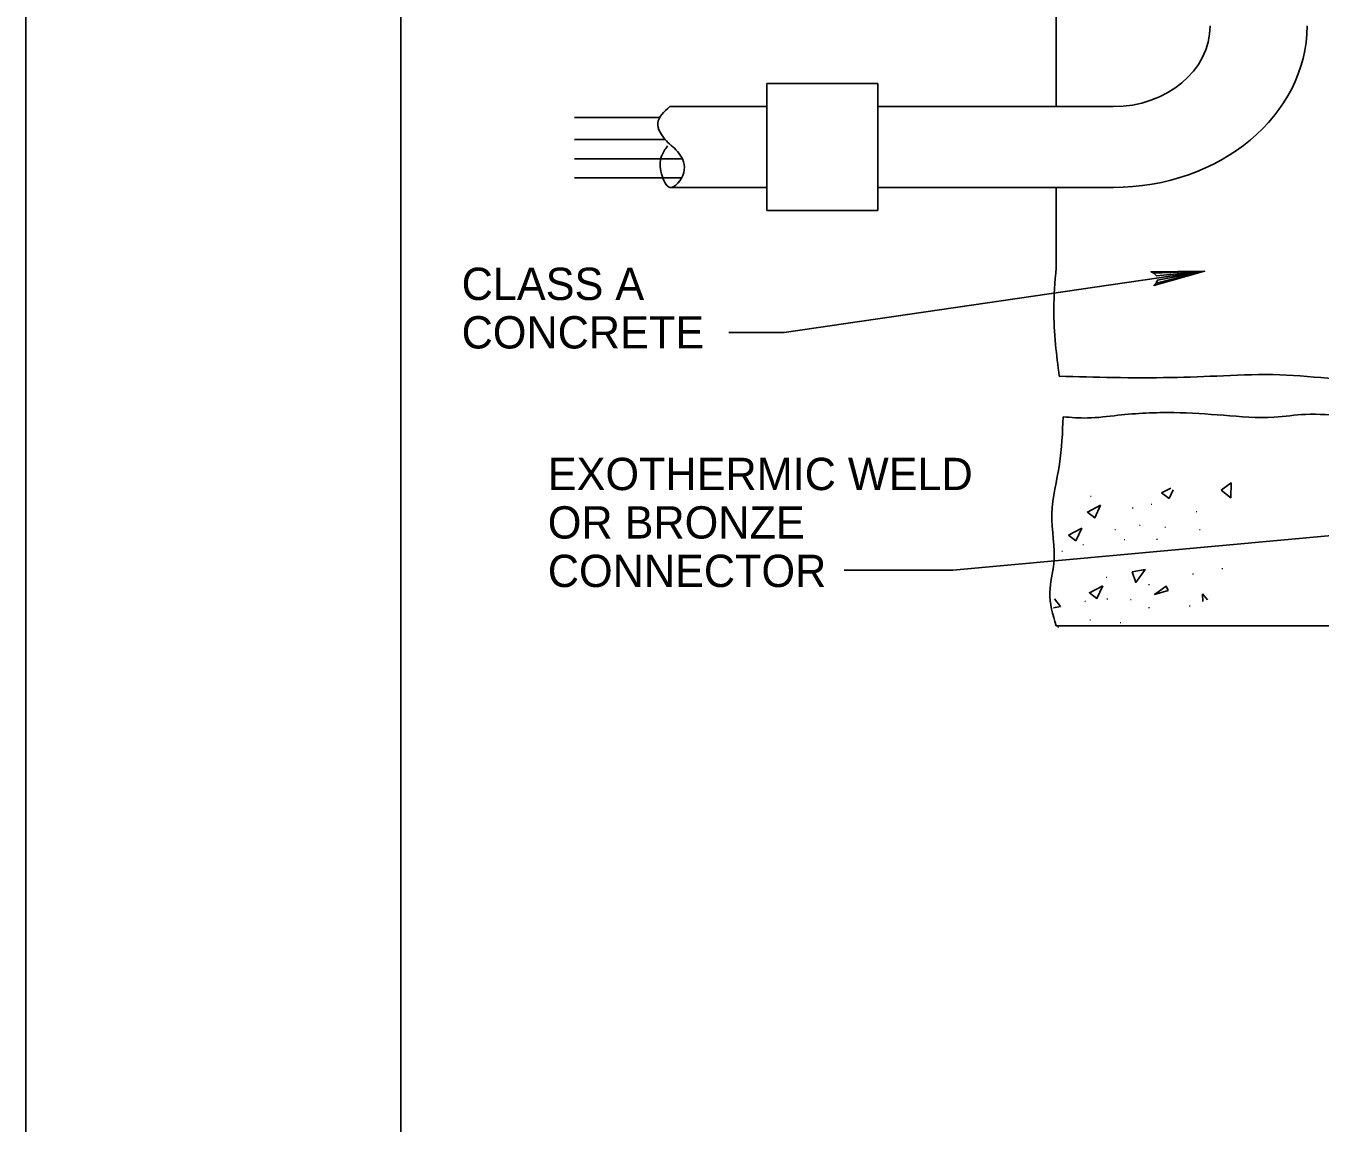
# Model space of a CAD drawing. Extents: x 638448 to 639352, y 297825 to 299013.
# Drawn here: x 638447.7 to 638582.2, y 298115.9 to 298230 of the extents above; entities that cross this region are included whole.
import ezdxf

# ---------------------------------------------------------------- set-up
doc = ezdxf.new("R2010")
doc.units = 0
for name, color, linetype in [('1', 7, 'Continuous'), ('2', 7, 'Continuous'), ('3', 7, 'Continuous'), ('PLT-BNDY', 7, 'Continuous')]:
    doc.layers.add(name, color=color, linetype=linetype)

msp = doc.modelspace()

# ---------------------------------------------------------------- linework, layer by layer
at = {"layer": '1'}
msp.add_lwpolyline([(639272.65, 297840.29), (639272.65, 298404.29), (638486.65, 298404.29), (638486.65, 297840.29), (639272.65, 297840.29), (639272.65, 297866.65), (639072.65, 297866.65), (639072.65, 297931.33), (639272.65, 297931.33), (639272.65, 297960.29), (639072.65, 297960.29), (639072.65, 297840.29), (639151.45, 297840.29), (639151.45, 297866.65), (639151.45, 297840.29), (639228.45, 297840.29), (639228.45, 297866.65), (639228.45, 297854.33), (639272.65, 297854.33)], dxfattribs=at)
at = {"layer": '2'}
for p, q in [((638554.77, 298256.25), (638554.77, 298221.59)), ((638513.54, 298220.45), (638504.71, 298220.45)), ((638524.7, 298221.59), (638514.62, 298221.59)), ((638560.7, 298221.59), (638536.22, 298221.59)), ((638514.16, 298218.17), (638504.71, 298218.17)), ((638515.9, 298216.18), (638504.71, 298216.18)), ((638515.75, 298214.18), (638504.71, 298214.18)), ((638524.7, 298213.19), (638514.62, 298213.19)), ((638560.7, 298213.19), (638536.22, 298213.19)), ((638554.77, 298213.19), (638554.77, 298204.79)), ((638554.77, 298167.59), (638589.14, 298167.59))]:
    msp.add_line(p, q, dxfattribs=at)
for points in [[(638536.22, 298210.79), (638536.22, 298223.99), (638524.7, 298223.99), (638524.7, 298210.79)], [(638571.94, 298181.71), (638572.97, 298182.46), (638572.93, 298180.91)], [(638559.4, 298180.15), (638558.02, 298179.43), (638558.8, 298178.84)], [(638562.67, 298173.22), (638564.02, 298173.45), (638563.05, 298172.11)], [(638559.62, 298171.76), (638558.24, 298171.04), (638559.02, 298170.45)], [(638566.44, 298171.27), (638566.2, 298171.73), (638565.01, 298170.87)]]:
    msp.add_lwpolyline(points, close=True, dxfattribs=at)
for points in [[(638520.74, 298198.11), (638526.5, 298198.11), (638570.21, 298204.48)], [(638564.95, 298204.27), (638565.2, 298203.99), (638570.21, 298204.48), (638564.95, 298204.27), (638564.64, 298204.42), (638570.21, 298204.48), (638565.3, 298203.56), (638565.18, 298203.22), (638570.21, 298204.48), (638564.94, 298202.98), (638565.18, 298203.22)], [(638566.7, 298181.91), (638565.74, 298181.41)], [(638565.74, 298181.41), (638566.52, 298180.83)], [(638566.52, 298180.83), (638566.94, 298181.74)], [(638532.72, 298173.38), (638544.04, 298173.38), (638589.14, 298177.5)], [(638557.43, 298177.74), (638556.05, 298177.02)], [(638556.83, 298176.43), (638557.43, 298177.74)], [(638556.05, 298177.02), (638556.83, 298176.43)], [(638570.03, 298170.12), (638570.01, 298170.93)], [(638570.01, 298170.93), (638570.51, 298170.29)], [(638555.24, 298169.6), (638554.51, 298169.46)], [(638554.62, 298170.4), (638555.24, 298169.6)]]:
    msp.add_lwpolyline(points, dxfattribs=at)
for major_axis in [(10.08, 0), (20.16, 0)]:
    msp.add_ellipse((638560.7, 298229.99), major_axis=major_axis, ratio=0.833333, start_param=4.712389, end_param=6.283185, dxfattribs=at)
for points in [[(638514.62, 298221.59), (638513.35, 298219.88), (638514.25, 298218.05), (638515.54, 298216.77), (638516.05, 298214.73), (638514.62, 298213.19), (638513.74, 298214.62), (638513.74, 298216.44), (638514.38, 298217.52)], [(638554.77, 298204.79), (638554.53, 298200.52), (638554.72, 298196.86), (638555.09, 298193.56)], [(638555.09, 298193.56), (638560.74, 298193.42), (638566.69, 298193.42), (638572.18, 298193.6), (638578.02, 298193.7), (638583.74, 298193.32), (638590.58, 298193.51), (638595.07, 298193.89), (638601.8, 298193.04), (638604.83, 298193.79), (638611.79, 298193.32), (638615.94, 298193.7), (638620.43, 298193.42), (638624.24, 298193.89), (638628.68, 298193.56)], [(638628.84, 298189.38), (638625.25, 298189.21), (638616.61, 298189.77), (638607.19, 298189.58), (638596.19, 298189.86), (638588.9, 298189.12), (638580.71, 298189.58), (638577.46, 298189.3), (638572.18, 298189.49), (638567.02, 298189.77), (638561.19, 298189.49), (638558.05, 298189.21), (638555.5, 298189.34)], [(638555.5, 298189.34), (638555.12, 298184.4), (638554.33, 298179.24), (638554.53, 298174.09), (638554.12, 298171.1), (638554.77, 298167.59)]]:
    msp.add_spline(points, degree=3, dxfattribs=at)
at = {"layer": 'PLT-BNDY'}
msp.add_lwpolyline([(638447.65, 298419.29), (639288.65, 298419.29), (639288.65, 297825.29), (638447.65, 297825.29)], close=True, dxfattribs=at)

# ---------------------------------------------------------------- texts
at = {"layer": '2'}
for p in [(638558.22, 298180.98), (638564.52, 298180.16), (638562.57, 298179.77), (638569.21, 298179.4), (638560.75, 298177.53), (638563.32, 298177.97), (638565.94, 298177.76), (638569.55, 298177.53), (638557.43, 298175.95), (638561.71, 298176.49), (638565.1, 298176.53), (638555.23, 298175.29), (638571.89, 298173.47), (638559.85, 298172.56), (638564.26, 298171.79), (638568.84, 298172.91), (638557.62, 298170.08), (638559.93, 298170.3), (638562.38, 298170.24), (638564.26, 298169.41), (638568.49, 298169.58), (638558.14, 298168.12), (638561.3, 298167.84), (638554.82, 298167.37)]:
    msp.add_text('.', height=0.893, dxfattribs=at).set_placement(p)
at = {"layer": '3'}
for s, p in [('CLASS A', (638492.96, 298201.48)), ('CONCRETE', (638492.96, 298196.44)), ('EXOTHERMIC WELD', (638501.92, 298181.71)), ('OR BRONZE', (638501.92, 298176.67)), ('CONNECTOR', (638501.92, 298171.63))]:
    msp.add_text(s, height=3.36, dxfattribs=at).set_placement(p)

doc.saveas('drawing.dxf')
